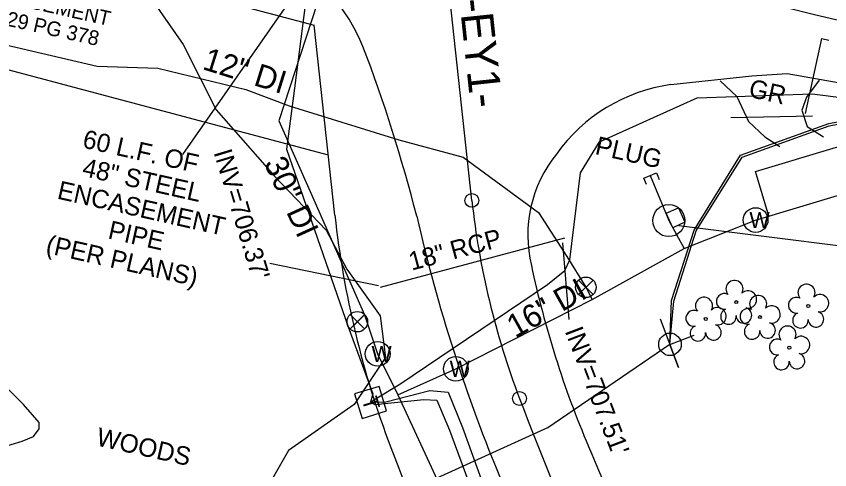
# Model space of a CAD drawing. Extents: x 1784037 to 1786391, y 840555 to 842045.
# Drawn here: x 1785567.5 to 1785744.6, y 841310.7 to 841409.5 of the extents above; entities that cross this region are included whole.
import ezdxf

# ---------------------------------------------------------------- set-up
doc = ezdxf.new("R2010")
doc.units = 0
for name, color, linetype in [('Exist Horizontal Alignment', 7, 'Continuous'), ('Exist Horizontal Alignment Direction Label', 7, 'Continuous'), ('Exist Horizontal Alignment Station Label', 7, 'Continuous'), ('Exist Hydro Stream or Body of Water', 7, 'Continuous'), ('Exist Other Culture Area Outline', 7, 'Continuous'), ('Exist Other Culture Area Outline Leader', 7, 'Continuous'), ('Exist Other Culture Area Outline Text', 7, 'Continuous'), ('Exist Right of Way Easement Line', 7, 'Continuous'), ('Exist Right of Way Easement Line Text', 7, 'Continuous'), ('Exist Right of Way Line', 7, 'Continuous'), ('Exist Roads EOP', 7, 'Continuous'), ('Exist Roads Soil', 7, 'Continuous'), ('Exist Roads Soil Text', 7, 'Continuous'), ('Exist Structure Minor Pipes RCP 12 Inch', 7, 'Continuous'), ('Exist Structure Minor Pipes RCP 12 Inch Text', 7, 'Continuous'), ('Exist Structure Minor Pipes RCP 18 Inch', 7, 'Continuous'), ('Exist Structure Minor Pipes RCP 18 Inch Invert', 7, 'Continuous'), ('Exist Structure Minor Pipes RCP 18 Inch Text', 7, 'Continuous'), ('Exist Utilities Power Joint Use Telephone CELL', 7, 'Continuous'), ('Exist Utilities Telephone Pedestal CELL', 7, 'Continuous'), ('Exist Utilities Telephone UG Cable SUE LOS B', 7, 'Continuous'), ('Exist Utilities TV UG Cable SUE LOS B', 7, 'Continuous'), ('Exist Utilities TV UG FO Cable SUE LOS B', 7, 'Continuous'), ('Exist Utilities Water Manhole CELL', 7, 'Continuous'), ('Exist Utilities Water UG Line SUE LOS B', 7, 'Continuous'), ('Exist Utilities Water UG Line SUE LOS B Text', 7, 'Continuous'), ('Exist Utilities Water UG Line SUE LOS C', 7, 'Continuous'), ('Exist Utilities Water Valve CELL', 7, 'Continuous'), ('Exist Utilities Water Valve Leader', 7, 'Continuous'), ('Exist Utilities Water Valve Text', 7, 'Continuous'), ('Exist Vegetation Tree CELL', 7, 'Continuous'), ('Exist Vegetation Woods Line', 7, 'Continuous'), ('Exist Vegetation Woods Line Text', 7, 'Continuous')]:
    doc.layers.add(name, color=color, linetype=linetype)

msp = doc.modelspace()

# ---------------------------------------------------------------- linework, layer by layer
at = {"layer": 'Exist Horizontal Alignment'}
msp.add_line((1785666.66, 841369.39), (1785659.91, 841431.24), dxfattribs=at)
for centre, radius, start, end in [((1786356.43, 843884.61), 2550, 255.06834, 261.97903), ((1785840.63, 841388.39), 175, 186.232, 200.8099), ((1786448.22, 841619.32), 825, 200.80994, 206.04741)]:
    msp.add_arc(centre, radius, start, end, dxfattribs=at)
at = {"layer": 'Exist Horizontal Alignment Station Label'}
for centre in [(1785666.66, 841369.39), (1785677.04, 841326.22), (1785677.04, 841326.22)]:
    msp.add_circle(centre, 1.5, dxfattribs=at)
at = {"layer": 'Exist Hydro Stream or Body of Water'}
msp.add_lwpolyline([(1785563.93, 841315.44), (1785568.72, 841316.94), (1785571.21, 841317.9), (1785572.44, 841319.58), (1785572.44, 841321.01), (1785569.06, 841324.9), (1785565, 841328.99)], dxfattribs=at)
at = {"layer": 'Exist Other Culture Area Outline'}
msp.add_circle((1785709.55, 841364.98), 3.49, dxfattribs=at)
at = {"layer": 'Exist Other Culture Area Outline Leader'}
msp.add_line((1785638.35, 841429.27), (1785603.64, 841379.39), dxfattribs=at)
at = {"layer": 'Exist Right of Way Easement Line'}
msp.add_line((1785419.99, 841436.66), (1785635.4, 841379.29), dxfattribs=at)
at = {"layer": 'Exist Right of Way Line'}
for p in [(1785415.62, 841465.34), (1785636.84, 841366.14)]:
    msp.add_line(p, (1785632.32, 841407.55), dxfattribs=at)
for centre, radius, start, end in [((1785840.63, 841388.39), 205, 186.232, 200.8099), ((1786448.22, 841619.32), 855, 200.80994, 206.04741)]:
    msp.add_arc(centre, radius, start, end, dxfattribs=at)
at = {"layer": 'Exist Roads EOP'}
msp.add_line((1785709.98, 841394.61), (1785727.59, 841396.53), dxfattribs=at)
msp.add_lwpolyline([(1785727.59, 841396.53), (1785735.34, 841397.07), (1785746.43, 841395.06), (1785789.97, 841386.7)], dxfattribs=at)
for centre, major_axis, ratio, start_param, end_param in [((1785600, 841384.58), (-33.42, 32.67), 0.999721, 4.319895, 5.071677), ((1785326.93, 841282.59), (-103.54, 327.45), 0.984636, 4.656083, 4.769152), ((1785715.15, 841358.03), (-12.63, 34.72), 0.99917, 6.074738, 6.886678), ((1785707, 841361.77), (12.93, -25.03), 0.999384, 3.55701, 4.470714), ((1785989.36, 841442.94), (49.85, -344.94), 0.9853, 4.793768, 4.968884), ((1785889.04, 841399.86), (-87.88, -195.43), 0.998917, 5.344473, 5.537917), ((1786622.45, 841735.84), (393.07, -1138.75), 0.846372, 4.790091, 4.839473)]:
    msp.add_ellipse(centre, major_axis=major_axis, ratio=ratio, start_param=start_param, end_param=end_param, dxfattribs=at)
at = {"layer": 'Exist Roads Soil'}
for points in [[(1785720.69, 841395.45), (1785724.33, 841392), (1785726.88, 841386.58), (1785730.45, 841383.22), (1785733.71, 841381.1)], [(1785742.28, 841395.55), (1785739.49, 841391.89), (1785738.51, 841389.02), (1785739.68, 841385.5), (1785743.21, 841383.26)]]:
    msp.add_lwpolyline(points, dxfattribs=at)
at = {"layer": 'Exist Structure Minor Pipes RCP 12 Inch'}
msp.add_line((1785723.05, 841387.43), (1785740.84, 841387.78), dxfattribs=at)
at = {"layer": 'Exist Structure Minor Pipes RCP 12 Inch Text'}
for p, q in [((1785739.33, 841388.33), (1785742.83, 841404.64)), ((1785742.83, 841404.64), (1785744.36, 841404.3))]:
    msp.add_line(p, q, dxfattribs=at)
at = {"layer": 'Exist Structure Minor Pipes RCP 18 Inch'}
msp.add_line((1785646.79, 841350.47), (1785686.88, 841361.22), dxfattribs=at)
at = {"layer": 'Exist Structure Minor Pipes RCP 18 Inch Invert'}
for p, q in [((1785686.41, 841360.11), (1785687.8, 841343.45)), ((1785646.36, 841350.78), (1785622.7, 841355.63))]:
    msp.add_line(p, q, dxfattribs=at)
at = {"layer": 'Exist Utilities Power Joint Use Telephone CELL'}
msp.add_line((1785709.79, 841338.02), (1785709.79, 841338.02), dxfattribs=at)
msp.add_lwpolyline([(1785707.69, 841343.57), (1785711.67, 841332.96), (1785709.77, 841338.01), (1785715.05, 841340.01)], dxfattribs=at)
msp.add_circle((1785709.8, 841338.02), 2.45, dxfattribs=at)
at = {"layer": 'Exist Utilities Telephone Pedestal CELL'}
msp.add_line((1785644.61, 841325.43), (1785644.61, 841325.43), dxfattribs=at)
msp.add_lwpolyline([(1785641.11, 841327.21), (1785642.75, 841321.86), (1785648.1, 841323.5), (1785646.46, 841328.85), (1785641.11, 841327.21)], dxfattribs=at)
at = {"layer": 'Exist Utilities Telephone UG Cable SUE LOS B'}
for points in [[(1785711.37, 841439.59), (1785636.12, 841452.54), (1785631.47, 841420.52), (1785628.05, 841393.86), (1785626.31, 841380.54), (1785639.73, 841341.8), (1785645.13, 841327.26), (1785644.61, 841325.43)], [(1785644.61, 841325.43), (1785645.69, 841326.11), (1785650.96, 841329.37), (1785683.11, 841351.09), (1785686.94, 841354.09), (1785688.01, 841356.42), (1785690.32, 841375.38), (1785694.46, 841382.13), (1785715.72, 841391.76), (1785740.77, 841392.59), (1785748.22, 841391.67), (1785751.5, 841399), (1785766.73, 841432.92)], [(1785644.61, 841325.43), (1785647.9, 841325.52), (1785657.52, 841327.98), (1785661.47, 841327.56), (1785664.59, 841319.9), (1785677.99, 841282.96), (1785697.86, 841244.57), (1785702.29, 841236.13)], [(1785644.61, 841325.43), (1785645.52, 841324.94), (1785656.19, 841325.97), (1785659.04, 841325.87), (1785661.78, 841319.28), (1785675.44, 841282.34), (1785694.51, 841243.43), (1785699.29, 841234.9)]]:
    msp.add_lwpolyline(points, dxfattribs=at)
at = {"layer": 'Exist Utilities TV UG Cable SUE LOS B'}
for points in [[(1785709.79, 841338.02), (1785710.13, 841347.55), (1785715.06, 841362.93), (1785725.15, 841379.22), (1785744.35, 841386.13), (1785757.26, 841388.59), (1785801.79, 841377.32), (1785835.53, 841367.86), (1785883.42, 841356.87), (1785888.55, 841352.97), (1785887.68, 841345.12)], [(1785622.54, 841298.59), (1785650.32, 841304.92), (1785683.17, 841319.9), (1785709.79, 841338.02)]]:
    msp.add_lwpolyline(points, dxfattribs=at)
at = {"layer": 'Exist Utilities TV UG FO Cable SUE LOS B'}
msp.add_lwpolyline([(1785709.79, 841338.02), (1785710.62, 841347.46), (1785715.52, 841362.72), (1785725.48, 841378.8), (1785744.49, 841385.64), (1785757.25, 841388.08), (1785801.66, 841376.84), (1785835.4, 841367.37), (1785883.31, 841356.39), (1785883.61, 841355.79), (1785886.68, 841352.59), (1785887.68, 841345.12)], dxfattribs=at)
at = {"layer": 'Exist Utilities Water Manhole CELL'}
for p, q in [((1785728.44, 841365.09), (1785728.44, 841365.09)), ((1785646.15, 841335.94), (1785646.15, 841335.94)), ((1785663.18, 841332.68), (1785663.18, 841332.68))]:
    msp.add_line(p, q, dxfattribs=at)
for centre in [(1785728.44, 841365.1), (1785646.15, 841335.94), (1785663.17, 841332.68)]:
    msp.add_circle(centre, 2.69, dxfattribs=at)
at = {"layer": 'Exist Utilities Water UG Line SUE LOS B'}
msp.add_line((1785643.26, 841344.47), (1785641.73, 841342.95), dxfattribs=at)
for points in [[(1785467.8, 841530.07), (1785514.16, 841519.18), (1785515.92, 841518.85), (1785578.2, 841508.18), (1785585.11, 841506.05), (1785602.38, 841501.15), (1785623.99, 841493.69), (1785648.17, 841485.72), (1785647.36, 841481.63), (1785643.74, 841471.66), (1785632.89, 841412.04), (1785624.66, 841386.69), (1785631.47, 841371.31), (1785643.26, 841344.47)], [(1785514.62, 841420.07), (1785552.97, 841406.13), (1785585.07, 841398.65), (1785598.28, 841398.19), (1785617.47, 841393.54), (1785626.9, 841389.99), (1785650.79, 841382.58), (1785664.76, 841378.82), (1785681.2, 841366.78), (1785687.37, 841357.13), (1785691.48, 841350.44), (1785692.85, 841347.81)], [(1785705.49, 841374.79), (1785709.55, 841364.98), (1785712.85, 841358.89)], [(1785650.58, 841326.98), (1785663.18, 841332.68), (1785692.85, 841347.81), (1785712.85, 841358.89), (1785728.44, 841365.09), (1785747.02, 841370.69)], [(1785643.26, 841344.47), (1785646.15, 841335.94), (1785650.58, 841326.98), (1785663.66, 841298.6), (1785682.66, 841256.17), (1785693.76, 841232.62)]]:
    msp.add_lwpolyline(points, dxfattribs=at)
at = {"layer": 'Exist Utilities Water UG Line SUE LOS C'}
msp.add_lwpolyline([(1785731.31, 841365.96), (1785728.43, 841375.66), (1785746.03, 841380.96), (1785749.47, 841380.07)], dxfattribs=at)
at = {"layer": 'Exist Utilities Water Valve CELL'}
for p, q in [((1785704.11, 841374.21), (1785705.49, 841374.79)), ((1785704.68, 841372.83), (1785704.11, 841374.21)), ((1785705.49, 841374.79), (1785706.88, 841375.36)), ((1785706.88, 841375.36), (1785707.45, 841373.97)), ((1785710.39, 841363.44), (1785708.98, 841366.6)), ((1785713.06, 841364.62), (1785710.39, 841363.44))]:
    msp.add_line(p, q, dxfattribs=at)
for points in [[(1785708.98, 841366.6), (1785711.66, 841367.78), (1785713.06, 841364.62)], [(1785693.05, 841352.02), (1785689.9, 841348.87), (1785691.48, 841350.44), (1785693.05, 841348.87), (1785689.9, 841352.02)], [(1785643.31, 841344.52), (1785640.16, 841341.37), (1785641.73, 841342.95), (1785643.31, 841341.37), (1785640.16, 841344.52)]]:
    msp.add_lwpolyline(points, dxfattribs=at)
for centre in [(1785691.48, 841350.44), (1785641.73, 841342.95)]:
    msp.add_circle(centre, 2.23, dxfattribs=at)
at = {"layer": 'Exist Utilities Water Valve Leader'}
msp.add_line((1785711.69, 841363.93), (1785753.53, 841358.67), dxfattribs=at)
at = {"layer": 'Exist Vegetation Tree CELL'}
for p, q in [((1785724.23, 841347.21), (1785724.23, 841347.21)), ((1785739.91, 841346.38), (1785739.91, 841346.38)), ((1785717.58, 841343.54), (1785717.58, 841343.54)), ((1785729.37, 841343.94), (1785729.37, 841343.94)), ((1785735.77, 841337.28), (1785735.77, 841337.28))]:
    msp.add_line(p, q, dxfattribs=at)
for centre in [(1785724.23, 841347.21), (1785739.91, 841346.38), (1785729.37, 841343.94), (1785717.58, 841343.54), (1785735.77, 841337.28)]:
    msp.add_circle(centre, 0.326, dxfattribs=at)
for centre, radius, start, end in [((1785723.84, 841350.08), 1.86, 330.1651, 219.7134), ((1785739.52, 841349.26), 1.86, 330.1651, 219.7134), ((1785726.77, 841347.79), 1.9, 257.1011, 134.1999), ((1785717.2, 841346.41), 1.86, 330.1651, 219.7134), ((1785721.62, 841347.36), 1.73, 62.6636, 279.3457), ((1785728.99, 841346.81), 1.86, 330.1651, 219.7134), ((1785737.3, 841346.54), 1.73, 62.6636, 279.3457), ((1785742.46, 841346.97), 1.9, 257.1011, 134.1999), ((1785720.13, 841344.13), 1.9, 257.1011, 134.1999), ((1785725.9, 841344.31), 1.7, 181.2822, 74.56), ((1785726.77, 841344.09), 1.73, 62.6636, 279.3457), ((1785731.92, 841344.53), 1.9, 257.1011, 134.1999), ((1785714.98, 841343.69), 1.73, 62.6636, 279.3457), ((1785722.52, 841344.08), 1.69, 111.5671, 6.231), ((1785738.2, 841343.26), 1.69, 111.5671, 6.231), ((1785741.58, 841343.48), 1.7, 181.2822, 74.56), ((1785719.25, 841340.64), 1.7, 181.2822, 74.56), ((1785727.67, 841340.82), 1.69, 111.5671, 6.231), ((1785731.05, 841341.04), 1.7, 181.2822, 74.56), ((1785715.88, 841340.42), 1.69, 111.5671, 6.231), ((1785735.39, 841340.15), 1.86, 330.1651, 219.7134), ((1785733.17, 841337.43), 1.73, 62.6636, 279.3457), ((1785738.32, 841337.87), 1.9, 257.1011, 134.1999), ((1785734.07, 841334.16), 1.69, 111.5671, 6.231), ((1785737.45, 841334.38), 1.7, 181.2822, 74.56)]:
    msp.add_arc(centre, radius, start, end, dxfattribs=at)
at = {"layer": 'Exist Vegetation Woods Line'}
msp.add_lwpolyline([(1785557.37, 841428.59), (1785570.39, 841427.86), (1785582.44, 841423.57), (1785594.29, 841417.1), (1785603.83, 841403.39), (1785611, 841389.09), (1785623.68, 841374.66), (1785634.97, 841362.92), (1785639.47, 841354.38), (1785646.71, 841344.25), (1785647.83, 841335.14), (1785641.06, 841324.9), (1785626.76, 841314.89), (1785616.63, 841297.25), (1785612.72, 841286.96), (1785601.71, 841277.8), (1785592.82, 841274.48), (1785585.4, 841280.1), (1785573.09, 841297.82), (1785560.8, 841304.2)], dxfattribs=at)

# ---------------------------------------------------------------- texts
at = {"layer": 'Exist Horizontal Alignment Direction Label'}
msp.add_text('-EY1-', height=7, rotation=276.0366, dxfattribs=at).set_placement((1785663.92, 841413.1))
at = {"layer": 'Exist Other Culture Area Outline Text'}
for s, p in [('60 L.F. OF', (1785581.69, 841380.94)), ('48" STEEL', (1785581.63, 841374.76)), ('ENCASEMENT', (1785576.19, 841369.8)), ('PIPE', (1785587.24, 841361.13)), ('(PER PLANS)', (1785573.71, 841357.98))]:
    msp.add_text(s, height=4, rotation=347.3599, dxfattribs=at).set_placement(p)
at = {"layer": 'Exist Right of Way Easement Line Text'}
for s, p in [('UTILITY EASEMENT', (1785547.93, 841416.29)), ('REF. DB 3929 PG 378', (1785542.87, 841412.5))]:
    msp.add_text(s, height=3.2, rotation=347.3599, dxfattribs=at).set_placement(p)
at = {"layer": 'Exist Roads Soil Text'}
msp.add_text('GR', height=4, rotation=347.3599, dxfattribs=at).set_placement((1785726.72, 841392))
at = {"layer": 'Exist Structure Minor Pipes RCP 18 Inch Invert'}
for s, rotation, p in [("INV=706.37'", 286.8902, (1785610.41, 841379.86)), ("INV=707.51'", 290.8425, (1785686.86, 841340.94))]:
    msp.add_text(s, height=4, rotation=rotation, dxfattribs=at).set_placement(p)
at = {"layer": 'Exist Structure Minor Pipes RCP 18 Inch Text'}
msp.add_text('18" RCP', height=4, rotation=15.007, dxfattribs=at).set_placement((1785653.55, 841354.07))
at = {"layer": 'Exist Utilities Telephone Pedestal CELL'}
msp.add_text('T', height=3.42, rotation=287.0506, dxfattribs=at).set_placement((1785642.64, 841326.01))
at = {"layer": 'Exist Utilities Water Manhole CELL'}
for p in [(1785727.09, 841363.34), (1785644.8, 841334.19), (1785661.82, 841330.93)]:
    msp.add_text('W', height=3.5, dxfattribs=at).set_placement(p)
at = {"layer": 'Exist Utilities Water UG Line SUE LOS B Text'}
for s, rotation, p in [('12" DI', 342.6057, (1785607.79, 841398.03)), ('30" DI', 294.5543, (1785621.33, 841377.53)), ('16" DI', 29.3382, (1785676.1, 841339.31))]:
    msp.add_text(s, height=5, rotation=rotation, dxfattribs=at).set_placement(p)
at = {"layer": 'Exist Utilities Water Valve Text'}
msp.add_text('PLUG', height=4, rotation=347.3599, dxfattribs=at).set_placement((1785693.29, 841379.5))
at = {"layer": 'Exist Vegetation Woods Line Text'}
msp.add_text('WOODS', height=4, rotation=347.3599, dxfattribs=at).set_placement((1785584.68, 841316.03))

doc.saveas('drawing.dxf')
